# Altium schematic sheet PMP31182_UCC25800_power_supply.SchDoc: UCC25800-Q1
size A3; Date: Not shown in title block; ApprovedBy: Not shown in title block; CheckedBy: Not shown in title block; Author: Not shown in title block; CompanyName: Not shown in title block; Engineer: Not shown in title block; Organization: Not shown in title block; Address1: Not shown in title block; Address2: Not shown in title block; Address3: Not shown in title block; Address4: Not shown in title block; DocumentNumber: 1; Revision: Use project parameter SCH_Rev; SheetNumber: 1; SheetTotal: 1; PageSetup: Record=PageOptions¦CenterHorizontal=True¦CenterVertical=True¦PrintScale=0.69¦XCorrection=1.00¦YCorrection=1.00¦PrintKind=0¦BorderSize=5000000¦LeftOffset=0¦BottomOffset=0¦Orientation=2¦PaperLength=1000¦PaperWidth=1000¦Scale=100¦PaperSource=15¦PrintQuality=600¦MediaType=1¦DitherType=10¦PaperKind=Letter¦PrintScaleMode=1
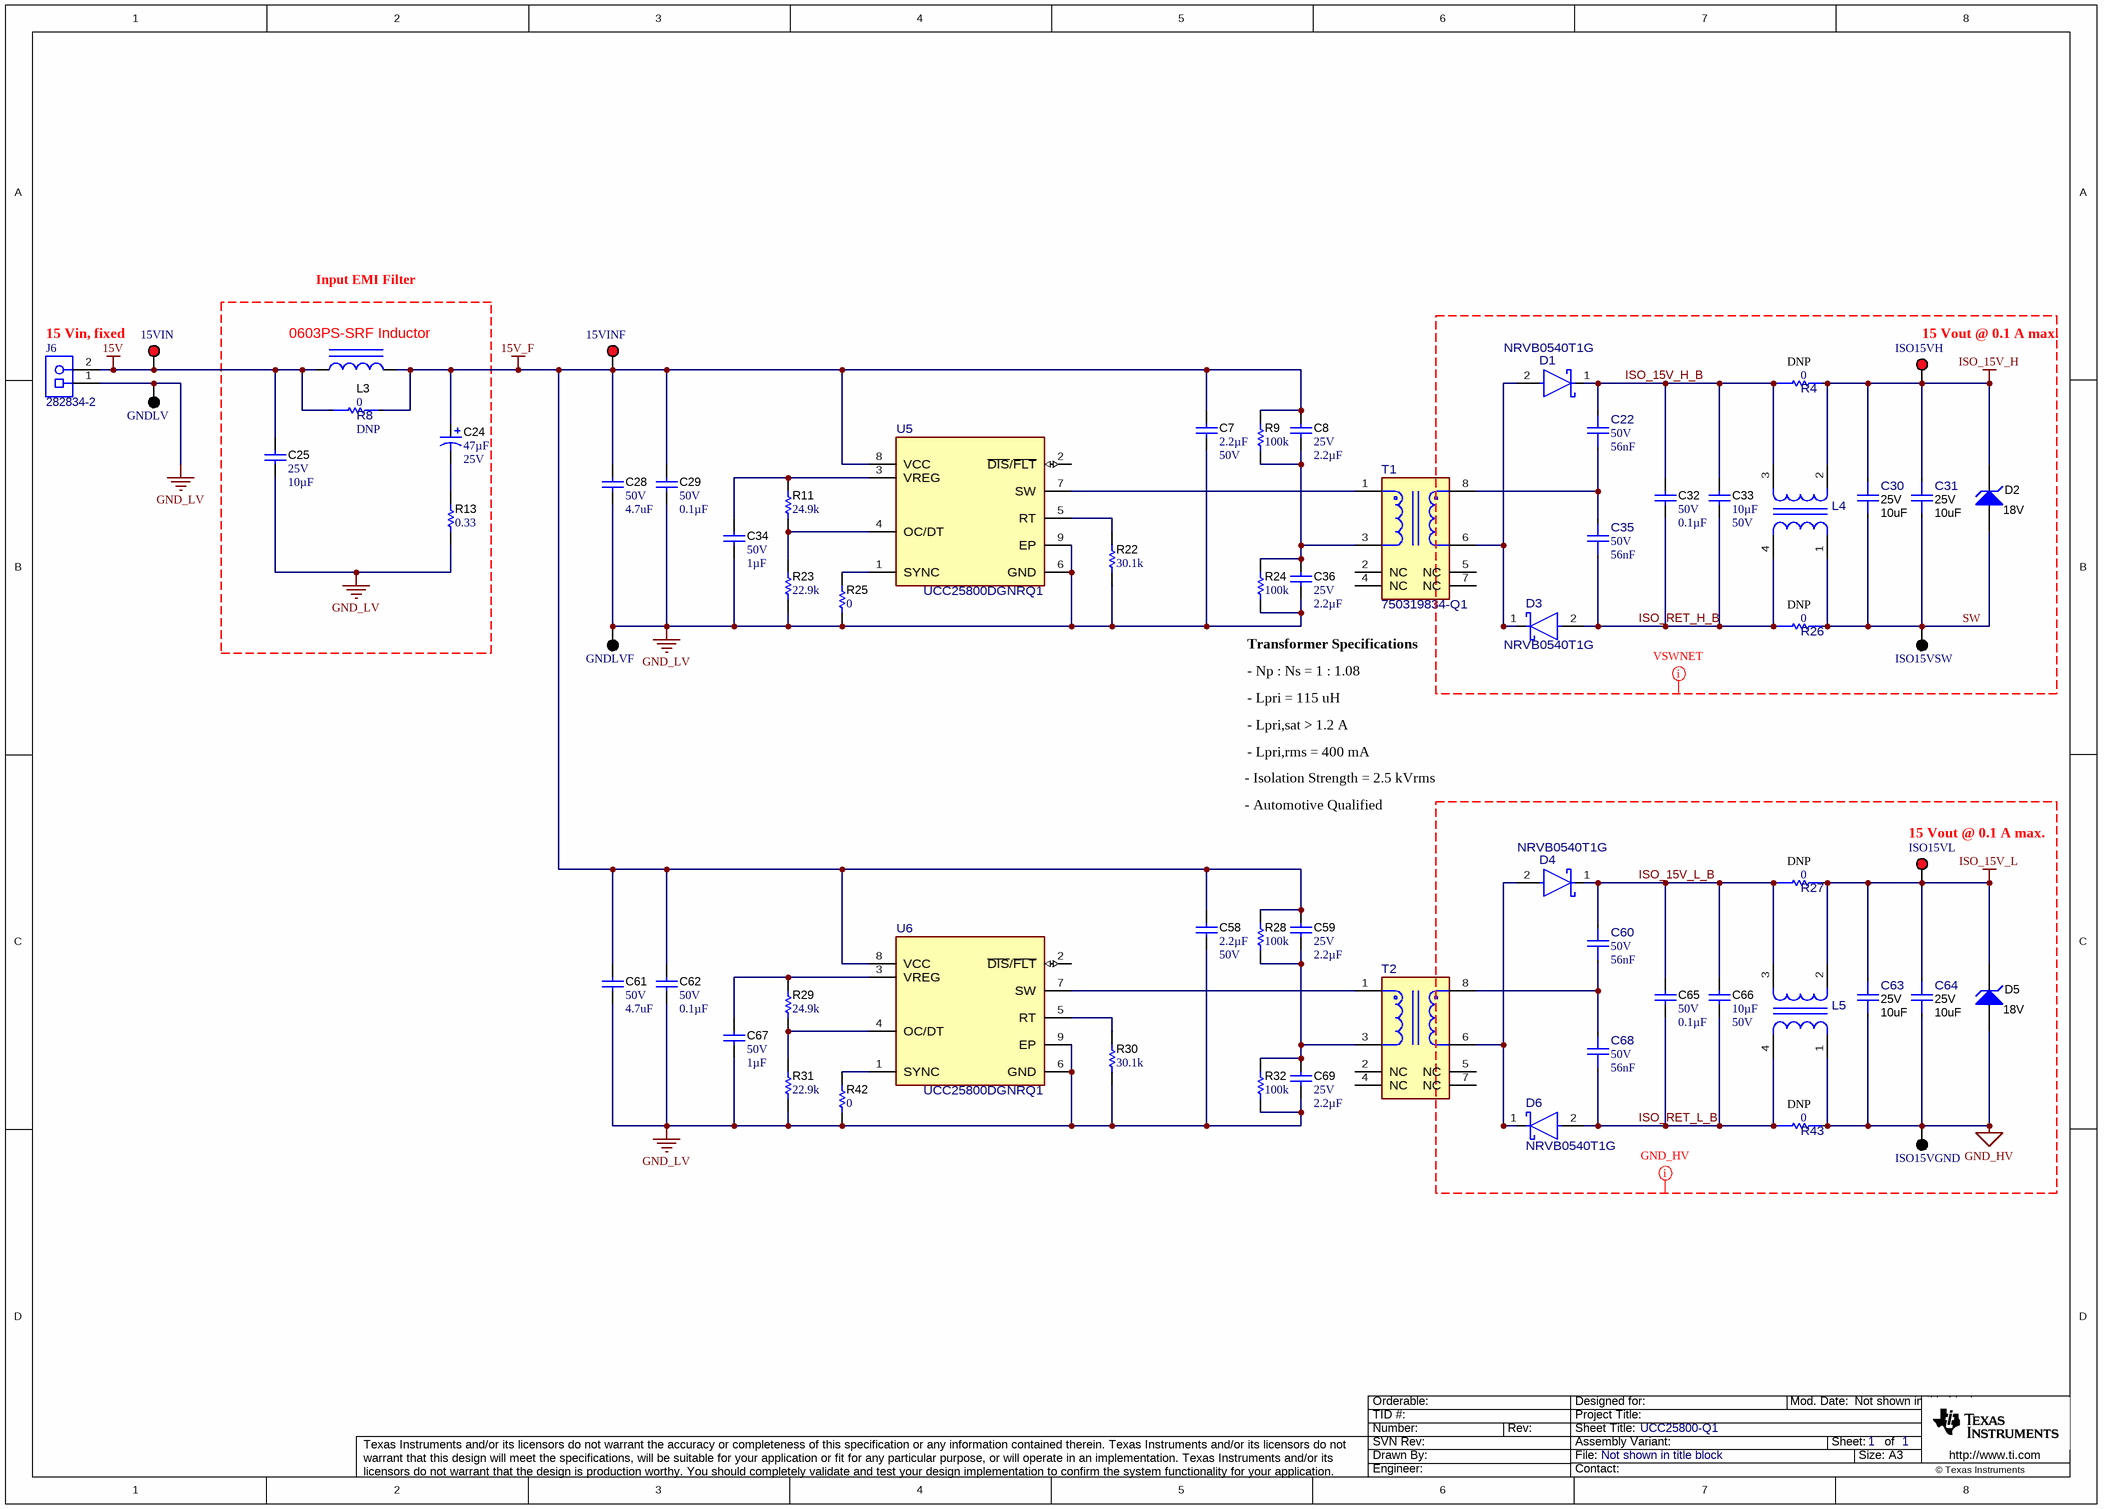
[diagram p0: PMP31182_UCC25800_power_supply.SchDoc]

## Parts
15VIN  5005  [Keystone5005]  (value not drawn)
15VINF  5005  [Keystone5005]  (value not drawn)
C7  Cap_F: 2.2µF  VDC_V: 50V  [0805_HV]  (hidden comment: C2012X7R1H225K125AC)
C8  VDC_V: 25V  ValueDisplayed: 2.2µF  [0603]  (hidden comment: GRM188C71E225KE11D)
C22  VDC_V: 50V  Cap_F: 56nF  [FP-C0603X563K5RACAUTO_0603-MFG]  (hidden comment: C0603X563K5RACAUTO)
C24  ValueDisplayed: 47µF  VDC_V: 25V  [HXB_F61]  (hidden comment: HHXC250ARA470MF61G)
C25  VDC_V: 25V  ValueDisplayed: 10µF  [1206_180]  (hidden comment: C1206C106J3RACAUTO)
C28  VDC_V: 50V  ValueDisplayed: 4.7uF  [1210_280]  (hidden comment: CGA6P3X7R1H475M250AB)
C29  VDC_V: 50V  ValueDisplayed: 0.1µF  [0603]  (hidden comment: CGA3E3X8R1H104K080AE)
C30  VDC_V: 25V  ValueDisplayed: 10uF  [FP-CGA4J1X7S1E106K125AC_0805-MFG]  (hidden comment: CGA4J1X7S1E106K125AC)
C31  VDC_V: 25V  ValueDisplayed: 10uF  [FP-CGA4J1X7S1E106K125AC_0805-MFG]  (hidden comment: CGA4J1X7S1E106K125AC)
C32  VDC_V: 50V  ValueDisplayed: 0.1µF  [0603]  (hidden comment: CGA3E3X8R1H104K080AE)
C33  ValueDisplayed: 10µF  VDC_V: 50V  [1206_190]  (hidden comment: CGA5L1X7R1H106K160AC)
C34  VDC_V: 50V  ValueDisplayed: 1µF  [0603]  (hidden comment: CGA3E3X5R1H105M080AB)
C35  VDC_V: 50V  Cap_F: 56nF  [FP-C0603X563K5RACAUTO_0603-MFG]  (hidden comment: C0603X563K5RACAUTO)
C36  VDC_V: 25V  ValueDisplayed: 2.2µF  [0603]  (hidden comment: GRM188C71E225KE11D)
C58  Cap_F: 2.2µF  VDC_V: 50V  [0805_HV]  (hidden comment: C2012X7R1H225K125AC)
C59  VDC_V: 25V  ValueDisplayed: 2.2µF  [0603]  (hidden comment: GRM188C71E225KE11D)
C60  VDC_V: 50V  Cap_F: 56nF  [FP-C0603X563K5RACAUTO_0603-MFG]  (hidden comment: C0603X563K5RACAUTO)
C61  VDC_V: 50V  ValueDisplayed: 4.7uF  [1210_280]  (hidden comment: CGA6P3X7R1H475M250AB)
C62  VDC_V: 50V  ValueDisplayed: 0.1µF  [0603]  (hidden comment: CGA3E3X8R1H104K080AE)
C63  VDC_V: 25V  ValueDisplayed: 10uF  [FP-CGA4J1X7S1E106K125AC_0805-MFG]  (hidden comment: CGA4J1X7S1E106K125AC)
C64  VDC_V: 25V  ValueDisplayed: 10uF  [FP-CGA4J1X7S1E106K125AC_0805-MFG]  (hidden comment: CGA4J1X7S1E106K125AC)
C65  VDC_V: 50V  ValueDisplayed: 0.1µF  [0603]  (hidden comment: CGA3E3X8R1H104K080AE)
C66  ValueDisplayed: 10µF  VDC_V: 50V  [1206_190]  (hidden comment: CGA5L1X7R1H106K160AC)
C67  VDC_V: 50V  ValueDisplayed: 1µF  [0603]  (hidden comment: CGA3E3X5R1H105M080AB)
C68  VDC_V: 50V  Cap_F: 56nF  [FP-C0603X563K5RACAUTO_0603-MFG]  (hidden comment: C0603X563K5RACAUTO)
C69  VDC_V: 25V  ValueDisplayed: 2.2µF  [0603]  (hidden comment: GRM188C71E225KE11D)
D1  NRVB0540T1G  [FP-NRVB0540T1G_SOD-123-MFG]
D2  value 18V  [SOD-123]  (hidden comment: BZT52C18-7-F)
D3  NRVB0540T1G  [FP-NRVB0540T1G_SOD-123-MFG]
D4  NRVB0540T1G  [FP-NRVB0540T1G_SOD-123-MFG]
D5  value 18V  [SOD-123]  (hidden comment: BZT52C18-7-F)
D6  NRVB0540T1G  [FP-NRVB0540T1G_SOD-123-MFG]
GNDLV  5006  [Keystone5006]  (value not drawn)
GNDLVF  5006  [Keystone5006]  (value not drawn)
ISO15VGND  5006  [Keystone5006]  (value not drawn)
ISO15VH  5005  [Keystone5005]  (value not drawn)
ISO15VL  5005  [Keystone5005]  (value not drawn)
ISO15VSW  5006  [Keystone5006]  (value not drawn)
J6  282834-2  [TEC_282834-2]
L3  0603PS-SRF Inductor  [0603AF]
L4  ACM2012-900-2P-T001  [FP-ACM2012-900-2P-T001_SMD4-MFG]  (value not drawn)
L5  ACM2012-900-2P-T001  [FP-ACM2012-900-2P-T001_SMD4-MFG]  (value not drawn)
R4  Res_ohm: 0  [FP-ERJ-3GEY0R00V_0603-MFG]  (hidden comment: ERJ-3GEY0R00V)
R8  Res_ohm: 0  [FP-ERJ-3GEY0R00V_0603-MFG]  (hidden comment: ERJ-3GEY0R00V)
R9  ValueDisplayed: 100k  [0603]  (hidden comment: RT0603BRD07100KL)
R11  ValueDisplayed: 24.9k  [0603]  (hidden comment: RT0603BRD0724K9L)
R13  ValueDisplayed: 0.33  [0603]  (hidden comment: ERJ-3RQFR33V)
R22  ValueDisplayed: 30.1k  [0603]  (hidden comment: RT0603BRD0730K1L)
R23  ValueDisplayed: 22.9k  [0603]  (hidden comment: RT0603DRE0722K9L)
R24  ValueDisplayed: 100k  [0603]  (hidden comment: RT0603BRD07100KL)
R25  ValueDisplayed: 0  [0603]  (hidden comment: RMCF0603ZT0R00)
R26  Res_ohm: 0  [FP-ERJ-3GEY0R00V_0603-MFG]  (hidden comment: ERJ-3GEY0R00V)
R27  Res_ohm: 0  [FP-ERJ-3GEY0R00V_0603-MFG]  (hidden comment: ERJ-3GEY0R00V)
R28  ValueDisplayed: 100k  [0603]  (hidden comment: RT0603BRD07100KL)
R29  ValueDisplayed: 24.9k  [0603]  (hidden comment: RT0603BRD0724K9L)
R30  ValueDisplayed: 30.1k  [0603]  (hidden comment: RT0603BRD0730K1L)
R31  ValueDisplayed: 22.9k  [0603]  (hidden comment: RT0603DRE0722K9L)
R32  ValueDisplayed: 100k  [0603]  (hidden comment: RT0603BRD07100KL)
R42  ValueDisplayed: 0  [0603]  (hidden comment: RMCF0603ZT0R00)
R43  Res_ohm: 0  [FP-ERJ-3GEY0R00V_0603-MFG]  (hidden comment: ERJ-3GEY0R00V)
T1  750319834-Q1  [FP-750319177r02_SMT_11MM21_11MM3-MFG]
T2  750319834-Q1  [FP-750319177r02_SMT_11MM21_11MM3-MFG]  (value not drawn)
U5  UCC25800DGNRQ1  [DGN0008G-MFG]
U6  UCC25800DGNRQ1  [DGN0008G-MFG]

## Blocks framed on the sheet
Input EMI Filter: C24 C25 L3 R8 R13

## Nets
15V: 15VIN.1 C25.1 J6.2 L3.1 R8.1
15V_F: 15VINF.1 C7.1 C8.1 C24.1(+) C28.1 C29.1 C58.1 C59.1 C61.1 C62.1 L3.2 R8.2 R9.2 R28.2 U5.8(VCC) U6.8(VCC)
GND_HV: C63.2 C64.2 D5.2(A) ISO15VGND.1 L5.1 R43.2
GND_LV: C7.2 C25.2 C28.2 C29.2 C34.2 C36.2 C58.2 C61.2 C62.2 C67.2 C69.2 GNDLV.1 GNDLVF.1 J6.1 R13.1 R22.1 R23.1 R24.1 R25.1 R30.1 R31.1 R32.1 R42.1 U5.6(GND) U5.9(EP) U6.6(GND) U6.9(EP)
ISO_15V_H: C30.1 C31.1 D2.1(K) ISO15VH.1 L4.2 R4.2
ISO_15V_L: C63.1 C64.1 D5.1(K) ISO15VL.1 L5.2 R27.2
ISO_15V_H_B: C22.2 C32.1 C33.1 D1.1(CATHODE) L4.3 R4.1
ISO_15V_L_B: C60.2 C65.1 C66.1 D4.1(CATHODE) L5.3 R27.1
ISO_RET_H_B: C32.2 C33.2 C35.1 D3.2(ANODE) L4.4 R26.1
ISO_RET_L_B: C65.2 C66.2 C68.1 D6.2(ANODE) L5.4 R43.1
SW: C30.2 C31.2 D2.2(A) ISO15VSW.1 L4.1 R26.2
NetC8_2: C8.2 C36.1 R9.1 R24.2 T1.3
NetC22_1: C22.1 C35.2 T1.8
NetC24_2: C24.2(-) R13.2
NetC34_1: C34.1 R11.2 U5.3(VREG)
NetC59_2: C59.2 C69.1 R28.1 R32.2 T2.3
NetC60_1: C60.1 C68.2 T2.8
NetC67_1: C67.1 R29.2 U6.3(VREG)
NetD1_2: D1.2(ANODE) D3.1(CATHODE) T1.6
NetD4_2: D4.2(ANODE) D6.1(CATHODE) T2.6
NetR11_1: R11.1 R23.2 U5.4(OC/DT)
NetR22_2: R22.2 U5.5(RT)
NetR25_2: R25.2 U5.1(SYNC)
NetR29_1: R29.1 R31.2 U6.4(OC/DT)
NetR30_2: R30.2 U6.5(RT)
NetR42_2: R42.2 U6.1(SYNC)
NetT1_1: T1.1 U5.7(SW)
NetT2_1: T2.1 U6.7(SW)

Not connected (* = marked no-connect by the designer): T1 2(NC) 4(NC) 5(NC) 7(NC); T2 2(NC) 4(NC) 5(NC) 7(NC); U5 2(~{DIS}/~{FLT}); U6 2(~{DIS}/~{FLT})

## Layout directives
net class VSWNET: ISO_15V_H, ISO_15V_H_B, ISO_RET_H_B, SW
net class PGND: GND_HV, ISO_15V_L, ISO_15V_L_B, ISO_RET_L_B

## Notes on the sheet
- 15 Vin, fixed
- (near R4) DNP
- (near ISO15VH) 15 Vout @ 0.1 A max.
- (near R8) DNP
- Transformer Specifications
- (near R26) DNP
- - Np : Ns = 1 : 1.08
- - Lpri = 115 uH
- - Isolation Strength = 2.5 kVrms
- - Lpri,sat > 1.2 A
- - Lpri,rms = 400 mA
- - Automotive Qualified
- (near ISO15VL) 15 Vout @ 0.1 A max.
- (near R27) DNP
- (near R43) DNP

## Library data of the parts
15VIN 15VINF ISO15VH ISO15VL = CMP-0055142-2: Test Point, Compact, Red, TH; Manufacturer: Keystone Electronics; CNHeader: FALSE; Green_Lifecycle: Active; Green_REACh: Passed; ContactFinish: Silver; CT: TRUE
C7 C58 = CMP-0007877-2: CAP, CERM, 2.2 uF, 50 V, +/- 10%, X7R, 0805; Manufacturer: TDK; TaMin_C: -55°C; ESR_ohm: 3.66m; Polarized: N; SizeAreaWB_mm2: 6.75; Value1: 0.00366 ohm; U/M: EA; Value: 2.2uF; TaMax_C: 125°C; SizeZ_mm: 1.45; SizeX_mm: 2; SizeY_mm: 1.25; Cap_Case: 0805; SizeArea_mm2: 2.5; IRMS_A: 3.41207A; AEC Category: Q200
C8 C36 C59 C69 = CMP-0075366-3: CAP, CERM, 2.2 µF, 25 V,+/- 10%, X7S, 0603; Manufacturer: MuRata; TaMin_C: -55°C; Polarized: N; SizeAreaWB_mm2: 4.68; U/M: EA; Value: 2.2uF; TaMax_C: 125°C; SizeZ_mm: 1.0; SizeX_mm: 1.6; SizeY_mm: 0.8; SizeArea_mm2: 1.28; AEC Category: Q200
C22 C35 C60 C68 = CMP-0093289-1: 0.056 µF ±10% 50V Ceramic Capacitor X7R 0603 (1608 Metric); Manufacturer: KEMET; Value: 56nF; TempCo: 15%; SizeZ_mm: 0.95mm; ValueDisplayed: 0.056uF; AEC Grade: Grade 1; AEC Qualified: Yes
C24 = CMP-0750159-1: CAP, AL, 47 µF, 25 V, +/- 20%, 0.05 ohm, AEC-Q200 Grade 1, SMD; Manufacturer: Chemi-Con; TaMin_C: -55°C; Cap_Case: 6.3x5.8mm; CompType: Capacitor; TaMax_C: 125°C; U/M: EA; Value: 47uF; AEC Grade: 1; AEC Category: Q200; AEC Qualified: Y; ESR_ohm: 0.05
C25 = CMP-0081062-1: CAP, CERM, 10 µF, 25 V,+/- 5%, X7R, AEC-Q200 Grade 1, 1206; Manufacturer: Kemet; TaMin_C: -55°C; Polarized: N; SizeAreaWB_mm2: 10.92; U/M: EA; Value: 10uF; TaMax_C: 125°C; SizeZ_mm: 1.8; SizeX_mm: 3.2; SizeY_mm: 1.6; SizeArea_mm2: 5.12; AEC Qualified: Y; AEC Grade: 1; AEC Category: Q200
C28 C61 = CMP-0009163-2: CAP, CERM, 4.7 uF, 50 V, +/- 20%, X7R, AEC-Q200 Grade 1, 1210; Manufacturer: TDK; TaMin_C: -55°C; Polarized: N; SizeAreaWB_mm2: 14.7; Value1: Unknown; U/M: EA; Value: 4.7uF; TaMax_C: 125°C; SizeZ_mm: 2.8; SizeX_mm: 3.2; SizeY_mm: 2.5; Cap_Case: 1210; SizeArea_mm2: 8; AEC Qualified: Y; Cap_F: 4.7µF; AEC Grade: 1; AEC Category: Q200
C29 C32 C62 C65 = CMP-0079911-1: CAP, CERM, 0.1 µF, 50 V,+/- 10%, X8R, AEC-Q200 Grade 0, 0603; Manufacturer: TDK; Cap_F: 100nF; SizeAreaWB_mm2: 4.68; SizeArea_mm2: 1.28; AEC Qualified: Y; AEC Category: Q200; Value: 0.1uF; TaMax_C: 150°C; SizeZ_mm: 1; AEC Grade: 0; Polarized: N; TaMin_C: -55°C; SizeY_mm: 0.8; U/M: EA; SizeX_mm: 1.6
C30 C31 C63 C64 = CMP-0091069-1: Cap Ceramic 10uF 25V X7S 10% Pad SMD 0805 +125°C Automotive T/R; Manufacturer: TDK Corporation; AEC Qualified: Yes; AEC Grade: Grade 1; Value: 10µF; Tolerance_%: 0.1%; SizeZ_mm: 1.45mm; TempCo: 22%
C33 C66 = CMP-0085950-1: CAP, CERM, 10 µF, 50 V,+/- 10%, X7R, AEC-Q200 Grade 1, 1206; Manufacturer: TDK; SizeZ_mm: 1.9; Value: 10uF; Cap_Case: 1206; AEC Grade: 1; TaMin_C: -55°C; U/M: EA; SizeArea_mm2: 5.12; TaMax_C: 125°C; AEC Qualified: Y; AEC Category: Q200; SizeX_mm: 3.2; SizeY_mm: 1.6; Polarized: N; SizeAreaWB_mm2: 10.92
C34 C67 = CMP-0083707-1: CAP, CERM, 1 µF, 50 V,+/- 20%, X5R, AEC-Q200 Grade 3, 0603; Manufacturer: TDK; SizeAreaWB_mm2: 4.68; SizeArea_mm2: 1.28; AEC Qualified: Y; AEC Category: Q200; Value: 1uF; TaMax_C: 85°C; SizeZ_mm: 1; AEC Grade: 3; Polarized: N; TaMin_C: -55°C; SizeY_mm: 0.8; U/M: EA; SizeX_mm: 1.6
D1 D3 D4 D6 = CMP-0090564-1: Diode Schottky 40V 500mA Surface Mount SOD-123; Manufacturer: On Semiconductor; Max Surge Forward Current: 5.5A; Standoff Height: 0mm; Import Ts: 1521847448; AEC Grade: Grade 0; AEC Qualified: Yes; Peak Reverse Current: 20uA; SizeZ_mm: 1.35mm; TJmax_C: 150°C; Ciiva Ids: 822523; Forward Current: 0.5A
D2 D5 = CMP-0084402-3: Diode, Zener, 18 V, 500 mW, AEC-Q101, SOD-123; Manufacturer: Diodes Inc.; SizeX_mm: 3.85; SizeAreaWB_mm2: 13.095; Green_REACh: Incomplete; AEC Category: Q101; AEC Qualified: Y; Value1: 0.5W; SizeY_mm: 1.7; Power_W: 500mW; SizeZ_mm: 1.35; RJA_CperW: 338; SizeArea_mm2: 6.545; Green_Lifecycle: Active
GNDLV GNDLVF ISO15VGND ISO15VSW = CMP-0055143-1: Test Point, Compact, Black, TH; Manufacturer: Keystone; CNHeader: FALSE; Green_Lifecycle: Active; Green_REACh: Passed; ContactFinish: Silver; CT: TRUE
J6 = CMP-0054974-1: Terminal Block, 2x1, 2.54mm, TH; Manufacturer: TE Connectivity; CNHeader: FALSE; Green_Lifecycle: Active; Green_REACh: Passed; CT: TRUE
L3 = CMP-0060122-1: Inductor, Wirewound, Ferrite, 240 nH, 0.85 A, 0.119999 ohm, SMD; Manufacturer: Coilcraft; PartNumber: 0603AF-241KRB; Irms: 0.85A @ 15C rise; Green_Lifecycle: Not Set; SizeAreaWB_mm2: 5.936; DCR_ohm: 1.19999d; Green_REACh: Incomplete; Value: 240nH; Imax_A: 8.5dA; SizeZ_mm: 0.91; SizeX_mm: 1.8; SizeY_mm: 1.12; Value2: 0.85A; SizeArea_mm2: 2.016; AEC Category: Q200
L4 L5 = CMP-0090488-1: 2 Line Common Mode Choke Surface Mount 90 Ohms @ 100MHz 400mA DCR 190mOhm; Manufacturer: TDK; SizeZ_mm: 1.3mm; DCR_ohm: 0.19; AEC Qualified: Yes; AEC Grade: Grade 2; Impedance At Frequency: 90Ω @ 100MHz
R4 R8 R26 R27 R43 = CMP-0089143-1: 0 Ohms Jumper 0.1W, 1/10W Chip Resistor 0603 (1608 Metric) Automotive AEC-Q200 Thick Film; Manufacturer: Panasonic; SizeZ_mm: 0.55mm; AEC Grade: Grade 0; VDC_V: 75V; TempCo: -100/+600ppm/°C; AEC Qualified: Yes; Power_W: 100mW; Tolerance_%: 5%
R9 R24 R28 R32 = CMP-0023630-3: RES, 100 k, 0.1%, 0.1 W, 0603; Manufacturer: Yageo America; Power_W: 100mW; TempCo: 25 ppm/C; U/M: EA; Value: 100k; EIA_Code: E192; SizeX_mm: 1.6; SizeY_mm: 0.8; SizeZ_mm: 1; Value2: 0.1W; SizeArea_mm2: 1.28; VDC_V: 75V; AEC Category: Q200
R11 R29 = CMP-0023990-3: RES, 24.9 k, 0.1%, 0.1 W, 0603; Manufacturer: Yageo America; Power_W: 100mW; TempCo: 25 ppm/C; Value_Code: 24k9; U/M: EA; Value: 24.9k; EIA_Code: E192; SizeX_mm: 1.6; SizeY_mm: 0.8; SizeZ_mm: 1; Value2: 0.1W; SizeArea_mm2: 1.28; VDC_V: 75V; AEC Category: Q200
R13 = CMP-0022714-3: RES, 0.33, 1%, 0.1 W, AEC-Q200 Grade 0, 0603; Manufacturer: Panasonic; Power_W: 100mW; TempCo: 300 ppm/C; Value_Code: R330; Value: 0.33; EIA_Code: E96; SizeX_mm: 1.6; SizeY_mm: 0.8; SizeZ_mm: 1; Value2: 0.1W; SizeArea_mm2: 1.28; AEC Qualified: Y; AEC Category: Q200; AEC Grade: 0; SizeAreaWB_mm2: 4.68
R22 R30 = CMP-0024096-3: RES, 30.1 k, 0.1%, 0.1 W, 0603; Manufacturer: Yageo America; Power_W: 100mW; TempCo: 25 ppm/C; Value_Code: 30k1; U/M: EA; Value: 30.1k; EIA_Code: E192; SizeX_mm: 1.6; SizeY_mm: 0.8; SizeZ_mm: 1; Value2: 0.1W; SizeArea_mm2: 1.28; VDC_V: 75V; AEC Category: Q200
R23 R31 = CMP-0024954-2: RES, 22.9 k, 0.5%, 0.1 W, 0603; Manufacturer: Yageo America; Power_W: 100mW; TempCo: 50 ppm/C; Value_Code: 22k9; U/M: EA; Value: 22.9k; EIA_Code: E192; SizeX_mm: 1.6; SizeY_mm: 0.8; SizeZ_mm: 1; Value2: 0.1W; SizeArea_mm2: 1.28; VDC_V: 75V; AEC Category: Q200
R25 R42 = CMP-0023343-3: RES, 0, 1%, 0.1 W, AEC-Q200 Grade 0, 0603; Manufacturer: Stackpole Electronics Inc; Power_W: 100mW; TempCo: ppm/C; U/M: EA; Value: 0; SizeX_mm: 1.6; SizeY_mm: 0.8; SizeZ_mm: 1; Value2: 0.1W; SizeArea_mm2: 1.28; AEC Qualified: Y; AEC Category: Q200
T1 T2 = CMP-0091345-1: Transformer, 1:1.67, 0.045Ohm Pri, 0.122Ohm Sec, 16.5uH; PartNumber: 750319177r02; Manufacturer: Wurth Electronics; AEC Qualified: No; Rsec1_ohm: 0.122; Ind_H: 16.5µH; Frequency_Fixed: 500kHz; SizeZ_mm: 12.2mm; DCR_ohm: 45m
U5 U6 = CMP-0088494-2: Open Loop LLC Transformer Driver for Isolated Bias Supplies; Manufacturer: Texas Instruments; Min Supply Voltage: 12V; SizeZ_mm: 1.1mm; Number Of Outputs: 1; Standoff Height: 0.05mm; AEC Category: Q200; Max Duty Cycle: 50%; TaMin_C: -40°C; TJmax_C: +150°C; AEC Qualified: No; Switching Frequency: 100-2000kHz; CompType: IC; Max Supply Voltage: 36V; TaMax_C: +125°C; Output Type: Other; Nominal Supply Current: 500uA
